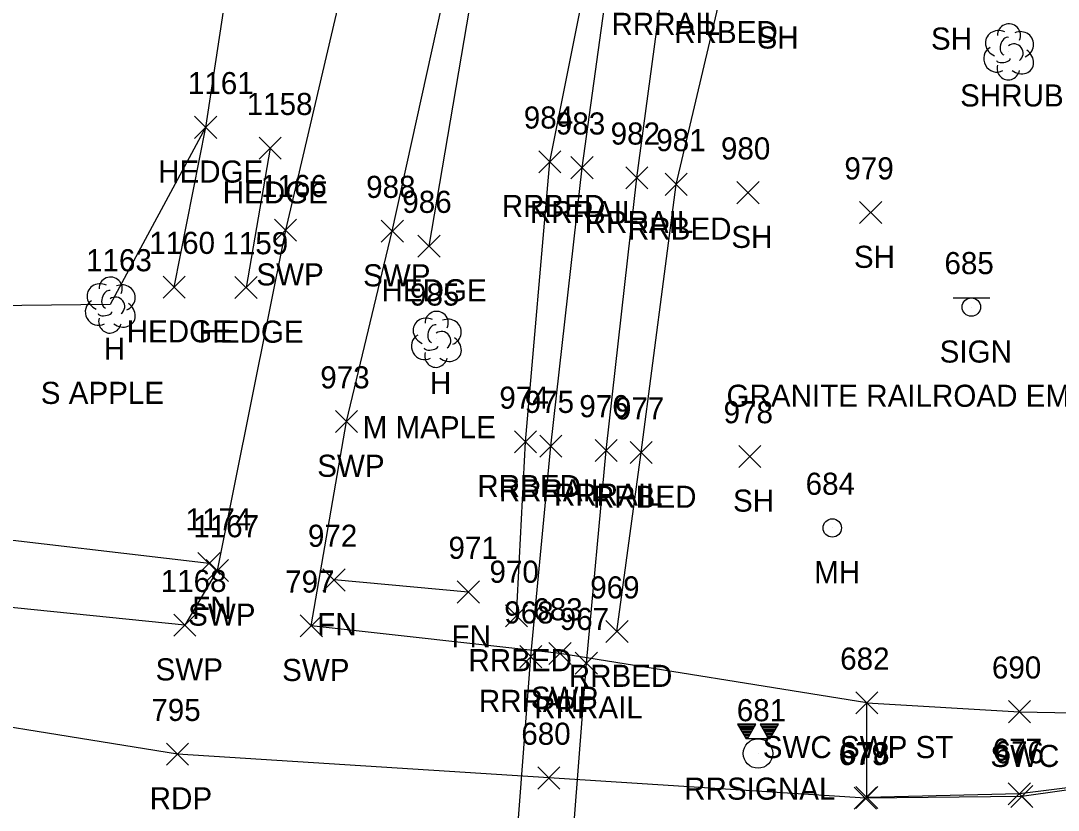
# Model space of a CAD drawing. Extents: x 1715662 to 1717487, y 887396 to 890004.
# Drawn here: x 1716426.1 to 1716519.9, y 888258 to 888329.4 of the extents above; entities that cross this region are included whole.
import ezdxf

# ---------------------------------------------------------------- set-up
doc = ezdxf.new("R2010")
doc.units = 0
for name, color, linetype in [('L_A', 7, 'Continuous'), ('L_C', 7, 'Continuous'), ('L_I', 7, 'Continuous'), ('L_TIC', 7, 'Continuous'), ('LAHR', 7, 'Continuous'), ('LFNC', 7, 'Continuous'), ('LSH', 7, 'Continuous'), ('LSOGP', 7, 'Continuous'), ('LTD', 7, 'Continuous'), ('P_A', 7, 'Continuous'), ('P_I', 7, 'Continuous'), ('P_TIC', 7, 'Continuous'), ('PET', 7, 'Continuous'), ('R_A', 7, 'Continuous'), ('R_I', 7, 'Continuous'), ('R_TIC', 7, 'Continuous'), ('RC', 7, 'Continuous'), ('RR', 7, 'Continuous'), ('RRB', 7, 'Continuous'), ('RSW', 7, 'Continuous'), ('S_A', 7, 'Continuous'), ('S_C', 7, 'Continuous'), ('S_I', 7, 'Continuous'), ('SSGN', 7, 'Continuous'), ('TCSH', 7, 'Continuous'), ('U_A', 7, 'Continuous'), ('U_I', 7, 'Continuous'), ('UUMH', 7, 'Continuous')]:
    doc.layers.add(name, color=color, linetype=linetype)

msp = doc.modelspace()

# ---------------------------------------------------------------- linework, layer by layer
at = {"layer": 'L_TIC'}
for points in [[(1716441.793, 888318.778), (1716443.793, 888320.778)], [(1716443.793, 888318.778), (1716441.793, 888320.778)], [(1716447.63, 888316.891), (1716449.63, 888318.891)], [(1716449.63, 888316.891), (1716447.63, 888318.891)], [(1716490.827, 888312.87), (1716492.827, 888314.87)], [(1716492.827, 888312.87), (1716490.827, 888314.87)], [(1716501.907, 888311.065), (1716503.907, 888313.065)], [(1716503.907, 888311.065), (1716501.907, 888313.065)], [(1716461.987, 888308.038), (1716463.987, 888310.038)], [(1716463.987, 888308.038), (1716461.987, 888310.038)], [(1716438.947, 888304.329), (1716440.947, 888306.329)], [(1716440.947, 888304.329), (1716438.947, 888306.329)], [(1716445.441, 888304.296), (1716447.441, 888306.296)], [(1716447.441, 888304.296), (1716445.441, 888306.296)], [(1716490.978, 888289.013), (1716492.978, 888291.013)], [(1716492.978, 888289.013), (1716490.978, 888291.013)], [(1716442.098, 888279.317), (1716444.098, 888281.317)], [(1716444.098, 888279.317), (1716442.098, 888281.317)], [(1716453.398, 888277.835), (1716455.398, 888279.835)], [(1716455.398, 888277.835), (1716453.398, 888279.835)], [(1716465.538, 888276.747), (1716467.538, 888278.747)], [(1716467.538, 888276.747), (1716465.538, 888278.747)]]:
    msp.add_lwpolyline(points, dxfattribs=at)
at = {"layer": 'LAHR'}
for points in [[(1716462.987, 888309.038), (1716467.622, 888336.156), (1716473.209, 888363.432), (1716480.225, 888389.651), (1716487.07, 888417.927), (1716491.695, 888439.81)], [(1716439.947, 888305.329), (1716442.793, 888319.778)], [(1716448.63, 888317.891), (1716446.441, 888305.296)]]:
    msp.add_lwpolyline(points, dxfattribs=at)
at = {"layer": 'LFNC'}
for points in [[(1716443.098, 888280.317), (1716420.433, 888282.989), (1716412.543, 888296.715), (1716401.348, 888315.282), (1716386.51, 888337.853), (1716374.785, 888353.899), (1716358.025, 888375.078), (1716341.376, 888394.001), (1716322.754, 888413.454), (1716303.71, 888431.095), (1716282.224, 888449.189), (1716263.808, 888463.099), (1716243.953, 888476.997), (1716231.603, 888485.189), (1716232.765, 888492.604)], [(1716466.538, 888277.747), (1716454.398, 888278.835)]]:
    msp.add_lwpolyline(points, dxfattribs=at)
at = {"layer": 'LSH'}
msp.add_line((1716515.369, 888326.662), (1716515.369, 888326.662), dxfattribs=at)
msp.add_line((1716515.369, 888326.662), (1716515.369, 888326.662), dxfattribs=at)
msp.add_arc((1716515.416, 888328.096), 1.047, 335.52715, 180.95627, dxfattribs=at)
for centre, major_axis, ratio, start_param, end_param in [((1716514.577, 888327.329), (1.21, -0.512), 0.895232, 1.570796, 4.712389), ((1716516.41, 888327.246), (-1.141, -0.483), 0.949671, 1.570796, 4.712389), ((1716515.16, 888327.12), (-0.208, -0.792), 0.645439, 3.141593, 6.283185), ((1716515.869, 888326.496), (-0.5, 0.667), 0.989748, 3.141593, 6.283185), ((1716514.286, 888325.954), (0.584, -1.042), 0.959034, 3.141593, 6.283185), ((1716516.369, 888325.829), (-1.09, 0.792), 0.841452, 1.570796, 4.712389), ((1716515.369, 888325.162), (0.265, 1.061), 0.942809, 1.570796, 4.712389), ((1716514.911, 888325.912), (-0.625, -0.083), 0.423636, 0, 3.141593)]:
    msp.add_ellipse(centre, major_axis=major_axis, ratio=ratio, start_param=start_param, end_param=end_param, dxfattribs=at)
at = {"layer": 'LSOGP'}
msp.add_lwpolyline([(1716469.007, 888433.308), (1716446.639, 888397.104), (1716439.784, 888394.85), (1716438.641, 888388.155), (1716443.71, 888383.152), (1716446.38, 888343.601), (1716442.786, 888319.775), (1716434.149, 888303.757), (1716410.201, 888303.478), (1716401.342, 888315.278), (1716398.071, 888328.134), (1716386.509, 888337.85), (1716374.78, 888353.896), (1716358.023, 888375.075), (1716341.376, 888394), (1716322.749, 888413.449)], dxfattribs=at)
at = {"layer": 'LTD'}
for p, q in [((1716434.149, 888303.759), (1716434.149, 888303.759)), ((1716434.149, 888303.759), (1716434.149, 888303.759)), ((1716463.629, 888300.654), (1716463.629, 888300.654)), ((1716463.629, 888300.654), (1716463.629, 888300.654))]:
    msp.add_line(p, q, dxfattribs=at)
for centre in [(1716434.196, 888305.193), (1716463.676, 888302.088)]:
    msp.add_arc(centre, 1.047, 335.52715, 180.95627, dxfattribs=at)
for centre, major_axis, ratio, start_param, end_param in [((1716433.357, 888304.426), (1.21, -0.512), 0.895232, 1.570796, 4.712389), ((1716435.191, 888304.343), (-1.141, -0.483), 0.949671, 1.570796, 4.712389), ((1716433.941, 888304.217), (-0.208, -0.792), 0.645439, 3.141593, 6.283185), ((1716433.066, 888303.051), (0.584, -1.042), 0.959034, 3.141593, 6.283185), ((1716434.649, 888303.593), (-0.5, 0.667), 0.989748, 3.141593, 6.283185), ((1716435.149, 888302.926), (-1.09, 0.792), 0.841452, 1.570796, 4.712389), ((1716433.691, 888303.009), (-0.625, -0.083), 0.423636, 0, 3.141593), ((1716434.15, 888302.259), (0.265, 1.061), 0.942809, 1.570796, 4.712389), ((1716462.837, 888301.321), (1.21, -0.512), 0.895232, 1.570796, 4.712389), ((1716463.421, 888301.112), (-0.208, -0.792), 0.645439, 3.141593, 6.283185), ((1716464.671, 888301.238), (-1.141, -0.483), 0.949671, 1.570796, 4.712389), ((1716462.546, 888299.946), (0.584, -1.042), 0.959034, 3.141593, 6.283185), ((1716464.129, 888300.488), (-0.5, 0.667), 0.989748, 3.141593, 6.283185), ((1716464.629, 888299.821), (-1.09, 0.792), 0.841452, 1.570796, 4.712389), ((1716463.63, 888299.154), (0.265, 1.061), 0.942809, 1.570796, 4.712389), ((1716463.171, 888299.904), (-0.625, -0.083), 0.423636, 0, 3.141593)]:
    msp.add_ellipse(centre, major_axis=major_axis, ratio=ratio, start_param=start_param, end_param=end_param, dxfattribs=at)
at = {"layer": 'P_TIC'}
for points in [[(1716439.241, 888262.084), (1716441.241, 888264.084)], [(1716441.241, 888262.084), (1716439.241, 888264.084)], [(1716472.824, 888259.93), (1716474.824, 888261.93)], [(1716474.824, 888259.93), (1716472.824, 888261.93)], [(1716501.433, 888258.092), (1716503.433, 888260.092)], [(1716503.433, 888258.092), (1716501.433, 888260.092)], [(1716515.575, 888258.254), (1716517.575, 888260.254)], [(1716517.575, 888258.254), (1716515.575, 888260.254)]]:
    msp.add_lwpolyline(points, dxfattribs=at)
at = {"layer": 'PET'}
msp.add_lwpolyline([(1716527, 888260.728), (1716516.575, 888259.254), (1716502.433, 888259.092), (1716473.824, 888260.93), (1716440.241, 888263.084), (1716411.867, 888267.674), (1716401.494, 888267.443), (1716378.307, 888267.153), (1716347.525, 888266.611), (1716339.044, 888266.533), (1716305.127, 888265.54), (1716291.61, 888264.06), (1716269.77, 888261.49)], dxfattribs=at)
at = {"layer": 'R_TIC'}
for points in [[(1716472.913, 888315.666), (1716474.913, 888317.666)], [(1716474.913, 888315.666), (1716472.913, 888317.666)], [(1716475.815, 888315.125), (1716477.815, 888317.125)], [(1716477.815, 888315.125), (1716475.815, 888317.125)], [(1716480.768, 888314.217), (1716482.768, 888316.217)], [(1716482.768, 888314.217), (1716480.768, 888316.217)], [(1716484.323, 888313.62), (1716486.323, 888315.62)], [(1716486.323, 888313.62), (1716484.323, 888315.62)], [(1716449.017, 888309.475), (1716451.017, 888311.475)], [(1716451.017, 888309.475), (1716449.017, 888311.475)], [(1716458.663, 888309.393), (1716460.663, 888311.393)], [(1716460.663, 888309.393), (1716458.663, 888311.393)], [(1716454.515, 888292.165), (1716456.515, 888294.165)], [(1716456.515, 888292.165), (1716454.515, 888294.165)], [(1716470.704, 888290.329), (1716472.704, 888292.329)], [(1716472.704, 888290.329), (1716470.704, 888292.329)], [(1716472.999, 888289.945), (1716474.999, 888291.945)], [(1716474.999, 888289.945), (1716472.999, 888291.945)], [(1716477.99, 888289.556), (1716479.99, 888291.556)], [(1716479.99, 888289.556), (1716477.99, 888291.556)], [(1716481.156, 888289.362), (1716483.156, 888291.362)], [(1716483.156, 888289.362), (1716481.156, 888291.362)], [(1716442.843, 888278.7), (1716444.843, 888280.7)], [(1716444.843, 888278.7), (1716442.843, 888280.7)], [(1716469.898, 888274.583), (1716471.898, 888276.583)], [(1716471.898, 888274.583), (1716469.898, 888276.583)], [(1716439.9, 888273.749), (1716441.9, 888275.749)], [(1716441.9, 888273.749), (1716439.9, 888275.749)], [(1716451.34, 888273.696), (1716453.34, 888275.696)], [(1716453.34, 888273.696), (1716451.34, 888275.696)], [(1716478.975, 888273.166), (1716480.975, 888275.166)], [(1716480.975, 888273.166), (1716478.975, 888275.166)], [(1716471.197, 888270.902), (1716473.197, 888272.902)], [(1716473.197, 888270.902), (1716471.197, 888272.902)], [(1716473.821, 888271.185), (1716475.821, 888273.185)], [(1716475.821, 888271.185), (1716473.821, 888273.185)], [(1716476.211, 888270.313), (1716478.211, 888272.313)], [(1716478.211, 888270.313), (1716476.211, 888272.313)], [(1716501.565, 888266.723), (1716503.565, 888268.723)], [(1716503.565, 888266.723), (1716501.565, 888268.723)], [(1716501.565, 888266.723), (1716503.565, 888268.723)], [(1716503.565, 888266.723), (1716501.565, 888268.723)], [(1716515.37, 888265.922), (1716517.37, 888267.922)], [(1716517.37, 888265.922), (1716515.37, 888267.922)], [(1716501.563, 888258.168), (1716503.563, 888260.168)], [(1716503.563, 888258.168), (1716501.563, 888260.168)], [(1716515.356, 888258.488), (1716517.356, 888260.488)], [(1716517.356, 888258.488), (1716515.356, 888260.488)], [(1716515.356, 888258.488), (1716517.356, 888260.488)], [(1716517.356, 888258.488), (1716515.356, 888260.488)]]:
    msp.add_lwpolyline(points, dxfattribs=at)
at = {"layer": 'RC'}
msp.add_lwpolyline([(1716585.127, 888301.696), (1716581.279, 888295.652), (1716577.778, 888291.12), (1716571.47, 888284.762), (1716564.345, 888278.599), (1716556.491, 888272.815), (1716548.069, 888268.083), (1716535.48, 888262.795), (1716527.014, 888260.806), (1716516.356, 888259.488)], dxfattribs=at)
at = {"layer": 'RR'}
for points in [[(1716461.02, 887983.964), (1716461.28, 888014.827), (1716461.928, 888036.879), (1716462.808, 888066.248), (1716463.195, 888072.918), (1716463.73, 888094.445), (1716464.225, 888116.344), (1716464.914, 888137.114), (1716465.909, 888167.56), (1716466.493, 888181.219), (1716467.401, 888200.131), (1716468.371, 888216.618), (1716469.676, 888239.096), (1716472.197, 888271.902), (1716473.999, 888290.945), (1716476.815, 888316.125), (1716479.363, 888334.44), (1716483.004, 888361.938), (1716487.306, 888387.934), (1716492.213, 888417.102)], [(1716461.974, 887885.395), (1716462.83, 887910.171), (1716464.449, 887957.376), (1716465.442, 887984.3), (1716466.282, 888014.511), (1716466.758, 888036.126), (1716467.795, 888066.641), (1716468.474, 888094.515), (1716469.094, 888116.578), (1716469.786, 888136.617), (1716470.876, 888167.552), (1716471.475, 888180.714), (1716472.375, 888199.713), (1716473.429, 888217.51), (1716474.73, 888238.997), (1716477.211, 888271.313), (1716478.99, 888290.556), (1716481.768, 888315.217), (1716484.181, 888333.138), (1716487.83, 888360.815), (1716492.094, 888386.989), (1716497.003, 888416.355)]]:
    msp.add_lwpolyline(points, dxfattribs=at)
at = {"layer": 'RRB'}
for points in [[(1716470.898, 888275.583), (1716471.704, 888291.329), (1716473.913, 888316.666), (1716477.503, 888334.613), (1716480.65, 888362.307), (1716484.977, 888388.603), (1716489.993, 888417.608), (1716492.841, 888440.672)], [(1716479.975, 888274.166), (1716482.156, 888290.362), (1716485.323, 888314.62), (1716489.502, 888332.398), (1716492.76, 888360.531), (1716495.872, 888386.518), (1716500.526, 888415.852), (1716503.554, 888440.103)]]:
    msp.add_lwpolyline(points, dxfattribs=at)
at = {"layer": 'RSW'}
for points in [[(1716476.683, 888425.515), (1716468.032, 888388.369), (1716466.749, 888382.232), (1716461.599, 888360.08), (1716450.017, 888310.475), (1716443.843, 888279.7), (1716440.9, 888274.749), (1716420.44, 888276.827), (1716417.678, 888279.005), (1716412.978, 888278.145), (1716400.217, 888275.488)], [(1716502.565, 888267.723), (1716474.821, 888272.185), (1716452.34, 888274.696), (1716455.515, 888293.165), (1716459.663, 888310.393), (1716465.466, 888336.81), (1716471.47, 888363.397), (1716477.614, 888389.845), (1716484.193, 888418.513)], [(1716516.356, 888259.488), (1716502.563, 888259.168), (1716502.565, 888267.723), (1716516.37, 888266.922), (1716524.362, 888266.76), (1716541.038, 888270.13), (1716552.023, 888276.045), (1716564.02, 888284.677), (1716573.093, 888293.522), (1716580.931, 888304.266), (1716586.199, 888313.472), (1716587.636, 888317.294), (1716588.867, 888321), (1716591.16, 888330.647), (1716592.415, 888340.136), (1716593.072, 888350.256), (1716593.216, 888359.766)]]:
    msp.add_lwpolyline(points, dxfattribs=at)
at = {"layer": 'SSGN'}
for p, q in [((1716510.364, 888304.353), (1716513.697, 888304.353)), ((1716512.011, 888303.519), (1716512.011, 888303.519))]:
    msp.add_line(p, q, dxfattribs=at)
msp.add_circle((1716512.011, 888303.519), 0.833, dxfattribs=at)
at = {"layer": 'TCSH'}
for p, q in [((1716492.543, 888265.803), (1716490.877, 888265.803)), ((1716490.877, 888265.803), (1716491.646, 888264.47)), ((1716491.774, 888264.47), (1716492.543, 888265.803)), ((1716494.578, 888265.803), (1716492.911, 888265.803)), ((1716492.911, 888265.803), (1716493.681, 888264.47)), ((1716493.808, 888264.47), (1716494.578, 888265.803)), ((1716493.808, 888264.47), (1716491.646, 888264.47)), ((1716492.727, 888263.137), (1716492.727, 888263.137))]:
    msp.add_line(p, q, dxfattribs=at)
for points in [[(1716490.921, 888265.727), (1716492.499, 888265.727)], [(1716490.998, 888265.593), (1716492.422, 888265.593)], [(1716491.075, 888265.46), (1716492.345, 888265.46)], [(1716491.152, 888265.327), (1716492.268, 888265.327)], [(1716492.939, 888265.755), (1716494.55, 888265.755)], [(1716493.016, 888265.622), (1716494.473, 888265.622)], [(1716493.093, 888265.488), (1716494.396, 888265.488)], [(1716493.17, 888265.355), (1716494.319, 888265.355)], [(1716491.229, 888265.193), (1716492.191, 888265.193)], [(1716491.306, 888265.06), (1716492.114, 888265.06)], [(1716491.383, 888264.927), (1716492.037, 888264.927)], [(1716491.46, 888264.793), (1716491.96, 888264.793)], [(1716491.537, 888264.66), (1716491.883, 888264.66)], [(1716491.614, 888264.527), (1716491.806, 888264.527)], [(1716493.247, 888265.222), (1716494.242, 888265.222)], [(1716493.324, 888265.088), (1716494.165, 888265.088)], [(1716493.401, 888264.955), (1716494.088, 888264.955)], [(1716493.478, 888264.822), (1716494.011, 888264.822)], [(1716493.555, 888264.688), (1716493.934, 888264.688)], [(1716493.632, 888264.555), (1716493.857, 888264.555)]]:
    msp.add_lwpolyline(points, dxfattribs=at)
msp.add_circle((1716492.727, 888263.137), 1.333, dxfattribs=at)
at = {"layer": 'UUMH'}
for p, q in [((1716499.443, 888283.54), (1716499.443, 888283.54)), ((1716500.276, 888283.54), (1716500.276, 888283.54))]:
    msp.add_line(p, q, dxfattribs=at)
msp.add_circle((1716499.443, 888283.54), 0.833, dxfattribs=at)

# ---------------------------------------------------------------- texts
at = {"layer": 'L_A'}
for s, p in [('SH', (1716492.683, 888326.902)), ('SH', (1716508.36, 888326.805)), ('SHRUB', (1716510.999, 888321.662)), ('HEDGE', (1716438.493, 888314.778)), ('HEDGE', (1716444.331, 888312.891)), ('SH', (1716490.315, 888308.87)), ('SH', (1716501.395, 888307.065)), ('HEDGE', (1716458.688, 888304.038)), ('HEDGE', (1716435.648, 888300.329)), ('HEDGE', (1716442.141, 888300.296)), ('H', (1716433.582, 888298.759)), ('H', (1716463.062, 888295.654)), ('SH', (1716490.466, 888285.013)), ('FN', (1716441.578, 888275.317)), ('FN', (1716452.879, 888273.835)), ('FN', (1716465.019, 888272.747))]:
    msp.add_text(s, height=2, dxfattribs=at).set_placement(p)
at = {"layer": 'L_C'}
for s, p in [('S APPLE', (1716427.882, 888294.759)), ('M MAPLE', (1716456.984, 888291.654))]:
    msp.add_text(s, height=2, dxfattribs=at).set_placement(p)
at = {"layer": 'L_I'}
for s, p in [('1161', (1716441.186, 888322.778)), ('1158', (1716446.504, 888320.891)), ('980', (1716489.378, 888316.87)), ('979', (1716500.537, 888315.065)), ('986', (1716460.57, 888312.038)), ('1160', (1716437.688, 888308.329)), ('1159', (1716444.307, 888308.296)), ('1163', (1716431.976, 888306.759)), ('985', (1716461.267, 888303.654)), ('978', (1716489.615, 888293.013)), ('1174', (1716440.972, 888283.317)), ('972', (1716452.036, 888281.835)), ('971', (1716464.743, 888280.747))]:
    msp.add_text(s, height=2, dxfattribs=at).set_placement(p)
at = {"layer": 'P_A'}
msp.add_text('RDP', height=2, dxfattribs=at).set_placement((1716437.73, 888258.084))
at = {"layer": 'P_I'}
for s, p in [('795', (1716437.879, 888266.084)), ('680', (1716471.328, 888263.93)), ('679', (1716500.015, 888262.092)), ('676', (1716514.11, 888262.254))]:
    msp.add_text(s, height=2, dxfattribs=at).set_placement(p)
at = {"layer": 'R_A'}
for s, p in [('RRRAIL', (1716479.473, 888328.138)), ('RRBED', (1716485.148, 888327.398)), ('RRBED', (1716469.559, 888311.666)), ('RRRAIL', (1716472.107, 888311.125)), ('RRRAIL', (1716477.059, 888310.217)), ('RRBED', (1716480.969, 888309.62)), ('SWP', (1716447.379, 888305.475)), ('SWP', (1716457.025, 888305.393)), ('SWP', (1716452.877, 888288.165)), ('RRBED', (1716467.35, 888286.329)), ('RRRAIL', (1716469.29, 888285.945)), ('RRRAIL', (1716474.282, 888285.556)), ('RRBED', (1716477.802, 888285.362)), ('SWP', (1716441.205, 888274.7)), ('RRBED', (1716466.543, 888270.583)), ('SWP', (1716438.262, 888269.749)), ('SWP', (1716449.702, 888269.696)), ('RRBED', (1716475.62, 888269.166)), ('SWP', (1716472.183, 888267.185)), ('RRRAIL', (1716467.489, 888266.902)), ('RRRAIL', (1716472.502, 888266.313)), ('SWC SWP ST', (1716493.156, 888262.723)), ('SWC SWP ST', (1716493.156, 888262.723)), ('SWC', (1716513.732, 888261.922)), ('RRSIGNAL', (1716486.054, 888258.959))]:
    msp.add_text(s, height=2, dxfattribs=at).set_placement(p)
at = {"layer": 'R_I'}
for s, p in [('984', (1716471.551, 888319.666)), ('983', (1716474.453, 888319.125)), ('982', (1716479.406, 888318.217)), ('981', (1716483.528, 888317.62)), ('1166', (1716447.788, 888313.475)), ('988', (1716457.3, 888313.393)), ('973', (1716453.153, 888296.165)), ('974', (1716469.342, 888294.329)), ('975', (1716471.636, 888293.945)), ('976', (1716476.573, 888293.556)), ('977', (1716479.794, 888293.362)), ('1167', (1716441.669, 888282.7)), ('970', (1716468.449, 888278.583)), ('1168', (1716438.727, 888277.749)), ('797', (1716449.978, 888277.696)), ('969', (1716477.557, 888277.166)), ('968', (1716469.788, 888274.902)), ('683', (1716472.412, 888275.185)), ('967', (1716474.801, 888274.313)), ('682', (1716500.156, 888270.723)), ('682', (1716500.156, 888270.723)), ('690', (1716513.874, 888269.922)), ('681', (1716490.809, 888266.059)), ('677', (1716513.947, 888262.488)), ('677', (1716513.947, 888262.488)), ('678', (1716500.154, 888262.168))]:
    msp.add_text(s, height=2, dxfattribs=at).set_placement(p)
at = {"layer": 'S_A'}
msp.add_text('SIGN', height=2, dxfattribs=at).set_placement((1716509.149, 888298.499))
at = {"layer": 'S_C'}
msp.add_text('GRANITE RAILROAD EMPLOYEE', height=2, dxfattribs=at).set_placement((1716489.881, 888294.499))
at = {"layer": 'S_I'}
msp.add_text('685', height=2, dxfattribs=at).set_placement((1716509.582, 888306.499))
at = {"layer": 'U_A'}
msp.add_text('MH', height=2, dxfattribs=at).set_placement((1716497.805, 888278.54))
at = {"layer": 'U_I'}
msp.add_text('684', height=2, dxfattribs=at).set_placement((1716497.033, 888286.54))

doc.saveas('drawing.dxf')
